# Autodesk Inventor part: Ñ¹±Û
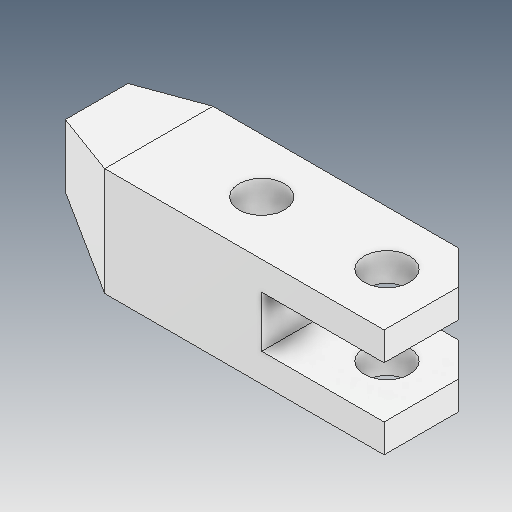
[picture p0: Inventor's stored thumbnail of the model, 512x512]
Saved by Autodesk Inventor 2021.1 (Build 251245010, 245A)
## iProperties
Created: 2021-05
Part Number: Ñ¹±Û
Material: Ogólny
Document SubType Name: Modeling
Designer: user
Density: 1 g/cm^3
Appearance: Domyślna
Author: user
Revision Number: ÈÎºÎ
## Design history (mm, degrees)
feature "ÊäÈë1"
node "Bryła1"
